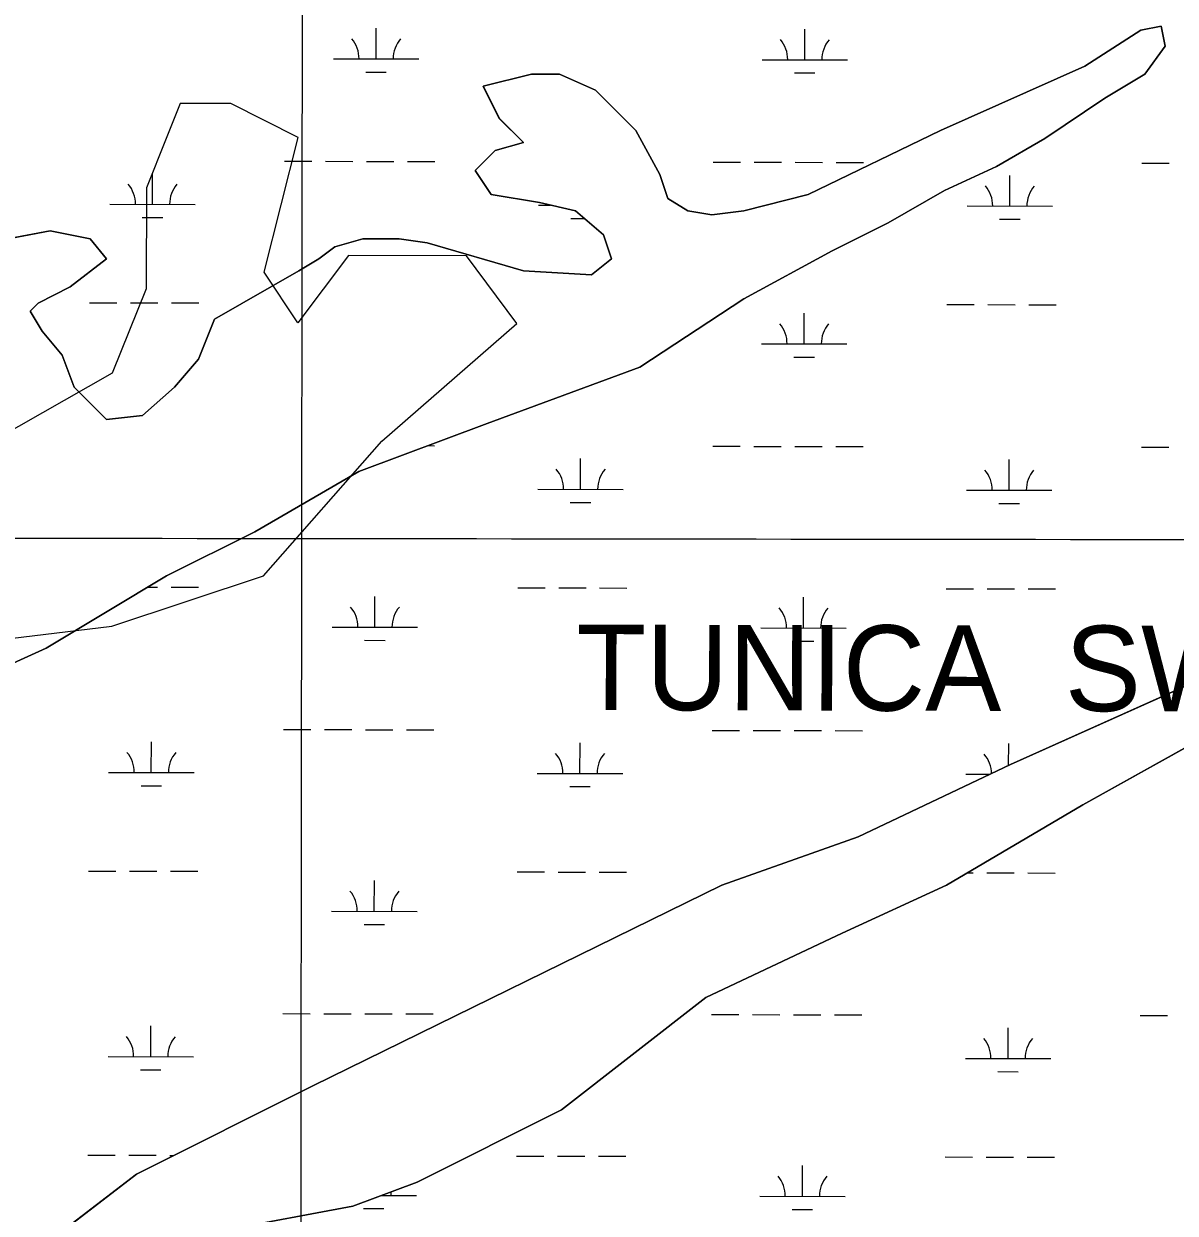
# Model space of a CAD drawing. Extents: x 3219052 to 3256913, y 800770 to 826146.
# Drawn here: x 3238621 to 3239969, y 817496 to 818889 of the extents above; entities that cross this region are included whole.
import ezdxf

# ---------------------------------------------------------------- set-up
doc = ezdxf.new("R2010")
doc.units = 0
for name, color, linetype in [('V-GRID-MAJR', 7, 'Continuous'), ('V-RIVR-IDEN', 7, 'Continuous'), ('V-SITE-VEGE', 7, 'Continuous'), ('V-TOPO-SHOR', 7, 'Continuous'), ('V-WETL-SWMP', 7, 'Continuous')]:
    doc.layers.add(name, color=color, linetype=linetype)

msp = doc.modelspace()

# ---------------------------------------------------------------- linework, layer by layer
at = {"layer": 'V-GRID-MAJR'}
for points in [[(3238932.375, 806165.204), (3238939.4250000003, 812223.951), (3238946.4790000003, 818286.164), (3238953.5330000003, 824348.415), (3238953.537, 824351.841)], [(3223238.921, 818307.868), (3228474.772, 818299.872), (3233710.625, 818292.637), (3238946.4790000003, 818286.164), (3244182.3340000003, 818280.452), (3249418.1890000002, 818275.502), (3254654.045, 818271.314), (3254654.046, 818271.314)]]:
    msp.add_spline(points, degree=3, dxfattribs=at)
at = {"layer": 'V-SITE-VEGE'}
for points in [[(3238595.468, 818134.171), (3238647.119, 818157.6680000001), (3238787.984, 818242.258), (3238891.285, 818293.954), (3239013.369, 818364.448), (3239163.626, 818420.8420000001), (3239342.056, 818486.638), (3239464.14, 818566.528), (3239567.441, 818622.922), (3239633.178, 818655.819), (3239698.914, 818693.414), (3239759.957, 818721.613), (3239816.304, 818754.508), (3239886.736, 818801.506), (3239933.691, 818829.702), (3239957.169, 818862.599), (3239952.473, 818886.096), (3239928.997, 818881.398), (3239863.258, 818839.101), (3239694.22, 818763.906), (3239539.267, 818688.716), (3239464.14, 818669.917), (3239426.575, 818665.2170000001), (3239398.401, 818669.917), (3239374.9250000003, 818684.0160000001), (3239365.5330000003, 818712.213), (3239337.36, 818763.906), (3239290.406, 818810.904), (3239248.145, 818829.702), (3239215.2770000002, 818829.702), (3239158.93, 818815.604), (3239177.713, 818778.007), (3239205.887, 818749.81), (3239173.017, 818740.412), (3239149.538, 818716.9130000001), (3239168.321, 818688.716), (3239224.667, 818679.318), (3239266.928, 818669.917), (3239299.796, 818641.721), (3239309.186, 818613.522), (3239285.71, 818594.725), (3239205.887, 818599.4230000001)], [(3239205.887, 818599.4230000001), (3239093.194, 818632.3200000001), (3239060.325, 818637.02), (3239018.0670000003, 818637.02), (3238985.197, 818627.622), (3238966.414, 818613.522), (3238942.936, 818599.4230000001), (3238844.329, 818543.029), (3238825.549, 818496.034), (3238797.374, 818463.139), (3238759.81, 818430.24), (3238717.552, 818425.542), (3238679.987, 818463.139), (3238665.901, 818500.734), (3238642.423, 818528.931), (3238628.3370000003, 818552.43), (3238637.7290000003, 818561.828), (3238675.291, 818580.627), (3238717.552, 818613.522), (3238698.769, 818637.02), (3238651.815, 818646.421), (3238576.686, 818632.3200000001)], [(3238856.0700000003, 817476.234), (3239006.326, 817504.431), (3239081.455, 817532.628), (3239250.492, 817617.221), (3239419.532, 817748.809), (3239579.18, 817823.9990000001), (3239701.2630000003, 817880.395), (3239860.911, 817974.386), (3240029.951, 818068.377), (3240189.595, 818115.372), (3240283.508, 818152.9670000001), (3240311.68, 818209.363), (3240283.508, 818237.56), (3240227.161, 818237.56), (3240152.032, 818199.965), (3240048.731, 818143.569), (3239776.392, 818021.381), (3239597.9620000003, 817936.789), (3239438.3140000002, 817880.395), (3238959.3710000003, 817645.4180000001), (3238752.769, 817542.029), (3238630.686, 817448.0380000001)]]:
    msp.add_lwpolyline(points, dxfattribs=at)
at = {"layer": 'V-TOPO-SHOR'}
msp.add_lwpolyline([(3238787.544080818, 818754.2792237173), (3238764.427742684, 818696.8378083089), (3238764.1794916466, 818578.3923657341), (3238724.49080159, 818479.770580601), (3238586.138951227, 818401.096578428), (3238467.610758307, 818361.863015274), (3238309.6421263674, 818342.4531095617), (3238250.378029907, 818322.8363279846), (3238250.295279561, 818283.354513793), (3238230.5129972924, 818263.6549818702), (3238289.611593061, 818204.3081350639), (3238565.9015420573, 818164.2470684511), (3238723.870173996, 818183.6569741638), (3238901.662463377, 818242.5073188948), (3239040.1798144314, 818400.1449494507), (3239198.3966974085, 818538.0002977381), (3239139.3394768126, 818617.0880516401), (3239001.153127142, 818617.3776778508), (3238941.764905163, 818538.5381749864), (3238902.40721649, 818597.8436466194), (3238942.220032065, 818755.6881530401), (3238863.339154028, 818795.3354679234), (3238804.1164327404, 818795.4595934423), (3238787.544080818, 818754.2792237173)], dxfattribs=at)
at = {"layer": 'V-WETL-SWMP'}
for p, q in [((3239033.4245650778, 818847.680680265), (3239033.500015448, 818883.6805689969)), ((3239535.3314621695, 818846.6287283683), (3239535.406912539, 818882.6286171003)), ((3239928.995785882, 818881.3910244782), (3239952.472785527, 818886.0900145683)), ((3239952.472785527, 818886.0900145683), (3239957.1687870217, 818862.5930562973)), ((3239863.257788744, 818839.0951043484), (3239928.995785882, 818881.3910244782)), ((3239957.168787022, 818862.5930562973), (3239933.6907891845, 818829.6961166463)), ((3238983.4246749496, 818847.7854755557), (3239083.4244552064, 818847.5758849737)), ((3239485.3315720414, 818846.7335236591), (3239585.3313522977, 818846.5239330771)), ((3239021.3922504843, 818832.2748788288), (3239045.3921977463, 818832.2245770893)), ((3239158.9297918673, 818815.5971915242), (3239215.2767908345, 818829.6961626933)), ((3239215.2767908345, 818829.6961626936), (3239248.1447907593, 818829.6961605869)), ((3239248.1447907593, 818829.6961605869), (3239290.404791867, 818810.8981915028)), ((3239523.2991475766, 818831.2229269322), (3239547.2990948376, 818831.1726251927)), ((3239694.2197939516, 818763.9022496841), (3239863.257788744, 818839.0951043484)), ((3239933.6907891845, 818829.6961166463), (3239886.7357910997, 818801.4991700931)), ((3239177.7117942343, 818778.0012575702), (3239158.9297918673, 818815.5971915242)), ((3239290.404791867, 818810.8981915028), (3239337.3597947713, 818763.902272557)), ((3239886.7357910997, 818801.4991700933), (3239816.3027942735, 818754.5032586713)), ((3239205.8857959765, 818749.8043062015), (3239177.7117942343, 818778.0012575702)), ((3239337.3597947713, 818763.902272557), (3239365.53279802, 818712.2073632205)), ((3239539.2667991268, 818688.710394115), (3239694.219793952, 818763.9022496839)), ((3239173.0167966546, 818740.4053251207), (3239205.8857959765, 818749.8043062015)), ((3239816.3027942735, 818754.5032586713), (3239759.9567965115, 818721.6073211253)), ((3239149.538798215, 818716.9073686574), (3239173.0167966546, 818740.4053251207)), ((3238926.329149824, 818727.8339863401), (3238958.3290795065, 818727.7669173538)), ((3238974.329044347, 818727.7333828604), (3239006.3289740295, 818727.6663138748)), ((3239022.3289388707, 818727.6327793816), (3239054.328868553, 818727.5657103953)), ((3239070.328833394, 818727.5321759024), (3239102.3287630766, 818727.4651069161)), ((3239168.320799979, 818688.7104178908), (3239149.538798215, 818716.9073686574)), ((3239428.236046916, 818726.7820344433), (3239460.2359765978, 818726.7149654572)), ((3239476.235941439, 818726.6814309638), (3239508.2358711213, 818726.614361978)), ((3239524.2358359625, 818726.5808274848), (3239556.235765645, 818726.5137584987)), ((3239572.235730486, 818726.4802240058), (3239604.235660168, 818726.4131550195)), ((3239759.9567965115, 818721.6073211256), (3239698.914798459, 818693.4093754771)), ((3239930.142944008, 818725.7300825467), (3239962.1428736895, 818725.6630135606)), ((3238771.631142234, 818677.4161534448), (3238771.7065926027, 818713.4160421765)), ((3239365.53279802, 818712.2073632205), (3239374.923799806, 818684.0104130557)), ((3239775.444936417, 818675.3122496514), (3239775.5203867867, 818711.3121383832)), ((3239224.667800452, 818679.3114310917), (3239168.320799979, 818688.7104178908)), ((3239464.138800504, 818669.9124325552), (3239539.2667991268, 818688.710394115)), ((3239698.914798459, 818693.4093754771), (3239633.1778010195, 818655.8134469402)), ((3238721.6312521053, 818677.5209487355), (3238821.6310323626, 818677.3113581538)), ((3239223.538149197, 818676.4689968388), (3239237.5800591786, 818676.4395662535)), ((3239266.9268009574, 818669.9124451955), (3239224.667800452, 818679.3114310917)), ((3239374.923799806, 818684.0104130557), (3239398.4018006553, 818669.9124367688)), ((3239725.4450462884, 818675.4170449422), (3239825.4448265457, 818675.2074543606)), ((3238759.5988276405, 818662.0103520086), (3238783.598774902, 818661.9600502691)), ((3239261.5057247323, 818660.9584001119), (3239277.4029409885, 818660.9250809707)), ((3239299.795802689, 818641.7144935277), (3239266.9268009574, 818669.9124451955)), ((3239398.4018006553, 818669.9124367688), (3239426.574800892, 818665.2124433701)), ((3239426.574800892, 818665.2124433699), (3239464.138800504, 818669.9124325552)), ((3239763.412621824, 818659.9064482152), (3239787.412569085, 818659.8561464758)), ((3238576.685804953, 818632.3155566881), (3238651.813803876, 818646.4145266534)), ((3238651.813803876, 818646.4145266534), (3238698.769804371, 818637.015540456)), ((3239633.1778010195, 818655.8134469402), (3239567.4408032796, 818622.9165099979)), ((3238698.769804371, 818637.015540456), (3238717.551805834, 818613.517581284)), ((3238985.1958043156, 818627.61653891), (3239018.0648036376, 818637.0155199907)), ((3239018.0648036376, 818637.0155199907), (3239060.3248035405, 818637.0155172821)), ((3239060.3248035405, 818637.0155172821), (3239093.192803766, 818632.3155235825)), ((3239093.192803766, 818632.3155235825), (3239205.8858056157, 818599.4185752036)), ((3239309.186804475, 818613.5175433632), (3239299.795802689, 818641.7144935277)), ((3238966.413805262, 818613.5175653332), (3238985.1958043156, 818627.61653891)), ((3239567.4408032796, 818622.9165099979), (3239464.138807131, 818566.5226174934)), ((3238717.551805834, 818613.517581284), (3238675.2918080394, 818580.620642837)), ((3238942.9368062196, 818599.4185920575), (3238966.4138052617, 818613.5175653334)), ((3239285.708805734, 818594.7195784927), (3239309.186804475, 818613.5175433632)), ((3238844.3308100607, 818543.0246992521), (3238942.9368062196, 818599.4185920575)), ((3239205.8858056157, 818599.4185752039), (3239285.708805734, 818594.7195784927)), ((3238675.2918080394, 818580.620642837), (3238637.7278093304, 818561.8226788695)), ((3239464.138807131, 818566.5226174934), (3239342.0558125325, 818486.6297682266)), ((3238637.7278093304, 818561.8226788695), (3238628.3368099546, 818552.4236962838)), ((3238628.3368099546, 818552.4236962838), (3238642.422811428, 818528.925737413)), ((3238697.981376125, 818562.1383664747), (3238729.9813058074, 818562.0712974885)), ((3238745.981270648, 818562.0377629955), (3238777.9812003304, 818561.9706940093)), ((3238793.9811651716, 818561.9371595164), (3238825.9810948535, 818561.8700905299)), ((3239534.6342274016, 818513.9547565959), (3239534.7096777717, 818549.9546453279)), ((3239701.795170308, 818560.0344626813), (3239733.795099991, 818559.9673936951)), ((3239749.7950648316, 818559.9338592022), (3239781.7949945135, 818559.866790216)), ((3239797.794959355, 818559.833255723), (3239829.794889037, 818559.7661867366)), ((3238825.5488131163, 818496.0297845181), (3238844.3308100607, 818543.0246992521)), ((3238642.422811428, 818528.925737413), (3238665.9008131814, 818500.7287863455)), ((3239484.634337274, 818514.0595518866), (3239584.63411753, 818513.8499613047)), ((3238665.9008131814, 818500.7287863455), (3238679.9868155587, 818463.1328526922)), ((3238797.3748152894, 818463.1328451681), (3238825.5488131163, 818496.0297845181)), ((3239522.6019128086, 818498.5489551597), (3239546.60186007, 818498.4986534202)), ((3239342.0558125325, 818486.6297682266), (3239163.625817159, 818420.83689735)), ((3238679.9868155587, 818463.1328526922), (3238717.551817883, 818425.5359175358)), ((3238759.810817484, 818430.2359064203), (3238797.3748152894, 818463.1328451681)), ((3238717.551817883, 818425.5359175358), (3238759.810817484, 818430.2359064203)), ((3239163.625817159, 818420.8368973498), (3239013.368821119, 818364.4420078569)), ((3239094.271304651, 818394.8065615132), (3239101.631528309, 818394.7911351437)), ((3239427.5388121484, 818394.1080626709), (3239459.5387418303, 818394.0409936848)), ((3239475.5387066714, 818394.0074591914), (3239507.5386363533, 818393.9403902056)), ((3239523.5386011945, 818393.9068557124), (3239555.5385308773, 818393.8397867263)), ((3239571.538495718, 818393.8062522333), (3239603.5384254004, 818393.7391832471)), ((3239929.44570924, 818393.0561107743), (3239961.4456389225, 818392.9890417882)), ((3239272.840804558, 818343.6902297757), (3239272.9162549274, 818379.6901185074)), ((3239774.7477016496, 818342.638277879), (3239774.8231520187, 818378.6381666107)), ((3239013.368821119, 818364.4420078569), (3238891.2858259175, 818293.9491417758)), ((3239222.8409144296, 818343.7950250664), (3239322.840694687, 818343.5854344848)), ((3239724.747811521, 818342.7430731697), (3239824.747591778, 818342.533482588)), ((3239260.8084899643, 818328.2844283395), (3239284.8084372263, 818328.2341266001)), ((3239762.7153870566, 818327.2324764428), (3239786.7153343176, 818327.1821747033)), ((3238891.2858259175, 818293.9491417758), (3238787.9838294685, 818242.2542408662)), ((3238787.9838294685, 818242.2542408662), (3238647.1188352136, 818157.6634012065)), ((3238766.4441398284, 818229.319441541), (3238777.283965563, 818229.2967222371)), ((3238793.2839304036, 818229.2631877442), (3238825.2838600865, 818229.1961187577)), ((3239199.1910384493, 818228.4124428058), (3239231.190968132, 818228.3453738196)), ((3239247.190932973, 818228.3118393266), (3239279.1908626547, 818228.2447703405)), ((3239295.1908274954, 818228.2112358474), (3239327.1907571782, 818228.1441668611)), ((3239032.030095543, 818182.3327367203), (3239032.1055459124, 818218.3326254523)), ((3239533.936992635, 818181.2807848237), (3239534.0124430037, 818217.2806735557)), ((3239701.097935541, 818227.3604909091), (3239733.0978652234, 818227.293421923)), ((3239749.0978300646, 818227.25988743), (3239781.0977597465, 818227.1928184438)), ((3239797.0977245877, 818227.1592839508), (3239829.0976542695, 818227.0922149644)), ((3238982.0302054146, 818182.4375320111), (3239082.029985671, 818182.2279414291)), ((3239483.9371025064, 818181.3855801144), (3239583.936882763, 818181.1759895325)), ((3239019.99778095, 818166.9269352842), (3239043.997728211, 818166.8766335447)), ((3239521.904678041, 818165.8749833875), (3239545.904625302, 818165.824681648)), ((3238647.1188352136, 818157.6634012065), (3238595.467836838, 818134.165446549)), ((3239776.3918413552, 818021.3765726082), (3240048.731832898, 818143.5643365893)), ((3238924.934680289, 818062.4860427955), (3238956.934609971, 818062.4189738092)), ((3238972.934574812, 818062.3854393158), (3239004.9345044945, 818062.3183703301)), ((3239020.9344693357, 818062.2848358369), (3239052.934399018, 818062.2177668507)), ((3239068.9343638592, 818062.1842323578), (3239100.934293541, 818062.1171633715)), ((3239426.841577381, 818061.4340908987), (3239458.841507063, 818061.3670219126)), ((3239474.841471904, 818061.3334874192), (3239506.8414015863, 818061.2664184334)), ((3239522.8413664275, 818061.2328839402), (3239554.8412961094, 818061.1658149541)), ((3239570.8412609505, 818061.1322804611), (3239602.841190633, 818061.0652114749)), ((3240029.949837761, 818068.3724722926), (3239860.9108441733, 817974.381651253)), ((3238770.2366726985, 818012.0682099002), (3238770.312123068, 818048.0680986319)), ((3239272.1435697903, 818011.0162580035), (3239272.21902016, 818047.0161467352)), ((3239774.072080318, 818020.276797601), (3239774.1259172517, 818045.9641948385)), ((3239597.961847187, 817936.784735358), (3239776.3918413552, 818021.3765726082)), ((3238720.23678257, 818012.1730051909), (3238820.236562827, 818011.9634146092)), ((3239222.1436796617, 818011.1210532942), (3239322.143459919, 818010.9114627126)), ((3239724.050576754, 818010.0691013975), (3239752.415535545, 818010.0096509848)), ((3238758.204358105, 817996.662408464), (3238782.2043053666, 817996.6121067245)), ((3239260.1112551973, 817995.6104565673), (3239284.1112024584, 817995.5601548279)), ((3239860.9108441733, 817974.381651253), (3239701.262850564, 817880.3908296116)), ((3239438.313851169, 817880.3908464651), (3239597.961847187, 817936.784735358)), ((3238696.58690659, 817896.7904229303), (3238728.5868362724, 817896.7233539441)), ((3238744.586801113, 817896.6898194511), (3238776.5867307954, 817896.622750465)), ((3238792.5866956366, 817896.589215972), (3238824.5866253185, 817896.5221469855)), ((3239198.493803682, 817895.7384710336), (3239230.493733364, 817895.6714020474)), ((3239246.493698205, 817895.6378675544), (3239278.493627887, 817895.5707985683)), ((3239294.493592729, 817895.5372640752), (3239326.4935224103, 817895.4701950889)), ((3239725.455580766, 817894.6340063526), (3239732.400630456, 817894.6194501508)), ((3239748.400595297, 817894.5859156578), (3239780.4005249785, 817894.5188466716)), ((3239796.40048982, 817894.4853121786), (3239828.4004195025, 817894.4182431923)), ((3238959.370867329, 817645.414297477), (3239438.313851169, 817880.3908464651)), ((3239031.3328607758, 817849.6587649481), (3239031.408311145, 817885.6586536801)), ((3239701.262850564, 817880.3908296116), (3239579.17985446, 817823.9959383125)), ((3238981.332970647, 817849.7635602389), (3239081.3327509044, 817849.5539696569)), ((3239019.300546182, 817834.252963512), (3239043.3004934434, 817834.2026617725)), ((3239579.17985446, 817823.9959383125), (3239419.531859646, 817748.8040830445)), ((3239419.531859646, 817748.8040830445), (3239250.492868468, 817617.2173292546)), ((3238924.2374455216, 817729.8120710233), (3238956.237375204, 817729.745002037)), ((3238972.237340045, 817729.7114675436), (3239004.237269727, 817729.644398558)), ((3239020.237234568, 817729.6108640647), (3239052.2371642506, 817729.5437950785)), ((3239068.2371290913, 817729.5102605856), (3239100.237058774, 817729.4431915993)), ((3239426.1443426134, 817728.7601191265), (3239458.1442722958, 817728.6930501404)), ((3239474.1442371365, 817728.659515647), (3239506.144166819, 817728.5924466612)), ((3239522.1441316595, 817728.558912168), (3239554.1440613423, 817728.4918431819)), ((3239570.144026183, 817728.458308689), (3239602.1439558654, 817728.3912397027)), ((3239928.051239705, 817727.7081672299), (3239960.0511693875, 817727.6410982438)), ((3238769.539437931, 817679.394238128), (3238769.6148883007, 817715.3941268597)), ((3239773.353232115, 817677.2903343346), (3239773.4286824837, 817713.2902230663)), ((3238719.539547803, 817679.4990334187), (3238819.53932806, 817679.289442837)), ((3239723.3533419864, 817677.3951296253), (3239823.3531222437, 817677.1855390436)), ((3238757.5071233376, 817663.9884366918), (3238781.5070705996, 817663.9381349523)), ((3239761.3209175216, 817661.8845328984), (3239785.3208647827, 817661.834231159)), ((3238752.767874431, 817542.0244956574), (3238959.370867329, 817645.414297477)), ((3239250.4928684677, 817617.2173292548), (3239081.454874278, 817532.6254914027)), ((3238695.8896718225, 817564.1164511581), (3238727.889601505, 817564.049382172)), ((3238743.8895663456, 817564.0158476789), (3238775.889496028, 817563.9487786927)), ((3238791.889460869, 817563.9152441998), (3238796.4926982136, 817563.9055962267)), ((3239197.7965689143, 817563.0644992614), (3239229.7964985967, 817562.9974302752)), ((3239245.796463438, 817562.9638957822), (3239277.7963931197, 817562.8968267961)), ((3239293.796357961, 817562.863292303), (3239325.796287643, 817562.7962233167)), ((3239699.703466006, 817562.0125473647), (3239731.703395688, 817561.9454783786)), ((3239747.703360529, 817561.9119438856), (3239779.703290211, 817561.8448748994)), ((3239795.7032550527, 817561.8113404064), (3239827.7031847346, 817561.7442714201)), ((3239532.5425230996, 817515.9328412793), (3239532.6179734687, 817551.9327300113)), ((3238630.6848807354, 817448.0336716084), (3238752.767874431, 817542.0244956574)), ((3239081.454874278, 817532.6254914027), (3239006.325876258, 817504.4285466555)), ((3239006.325876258, 817504.4285466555), (3238856.0698784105, 817476.2306067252)), ((3239039.730421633, 817516.9657312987), (3239080.6355161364, 817516.8799978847)), ((3239482.542632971, 817516.03763657), (3239582.542413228, 817515.8280459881)), ((3239018.6033114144, 817501.5789917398), (3239042.6032586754, 817501.5286900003)), ((3239520.5102085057, 817500.5270398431), (3239544.5101557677, 817500.4767381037))]:
    msp.add_line(p, q, dxfattribs=at)
for centre, radius, start, end in [((3238978.1827454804, 818848.2712659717), 35.24628790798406, 359.1080939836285, 40.65175231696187), ((3239088.6683749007, 818848.0396979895), 35.246287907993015, 139.10808960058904, 180.65174793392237), ((3239480.0896425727, 818847.219314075), 35.24628790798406, 359.1080939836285, 40.65175231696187), ((3239590.575271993, 818846.9877460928), 35.246287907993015, 139.10808960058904, 180.65174793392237), ((3238716.389322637, 818678.0067391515), 35.24628790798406, 359.1080939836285, 40.65175231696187), ((3238826.874952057, 818677.7751711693), 35.246287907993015, 139.10808960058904, 180.65174793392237), ((3239720.20311682, 818675.9028353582), 35.24628790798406, 359.1080939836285, 40.65175231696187), ((3239830.68874624, 818675.6712673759), 35.246287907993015, 139.10808960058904, 180.65174793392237), ((3239479.3924078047, 818514.5453423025), 35.24628790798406, 359.1080939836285, 40.65175231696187), ((3239589.878037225, 818514.3137743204), 35.246287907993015, 139.10808960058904, 180.65174793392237), ((3239217.5989849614, 818344.2808154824), 35.24628790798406, 359.1080939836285, 40.65175231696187), ((3239328.0846143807, 818344.0492475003), 35.246287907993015, 139.10808960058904, 180.65174793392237), ((3239719.505882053, 818343.2288635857), 35.24628790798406, 359.1080939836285, 40.65175231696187), ((3239829.991511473, 818342.9972956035), 35.246287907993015, 139.10808960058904, 180.65174793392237), ((3238976.788275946, 818182.9233224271), 35.24628790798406, 359.1080939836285, 40.65175231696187), ((3239087.273905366, 818182.6917544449), 35.246287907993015, 139.10808960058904, 180.65174793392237), ((3239478.6951730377, 818181.8713705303), 35.24628790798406, 359.1080939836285, 40.65175231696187), ((3239589.1808024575, 818181.6398025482), 35.246287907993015, 139.10808960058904, 180.65174793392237), ((3238714.9948531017, 818012.6587956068), 35.24628790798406, 359.1080939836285, 40.65175231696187), ((3238825.4804825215, 818012.4272276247), 35.246287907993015, 139.10808960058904, 180.65174793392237), ((3239216.9017501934, 818011.6068437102), 35.24628790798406, 359.1080939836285, 40.65175231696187), ((3239327.3873796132, 818011.3752757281), 35.246287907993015, 139.10808960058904, 180.65174793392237), ((3239718.8086472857, 818010.5548918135), 35.24628790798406, 0.3765230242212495, 40.651752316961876), ((3239829.294276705, 818010.3233238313), 35.246287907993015, 139.10808960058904, 139.9364566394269), ((3238976.0910411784, 817850.2493506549), 35.24628790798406, 359.1080939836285, 40.65175231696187), ((3239086.5766705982, 817850.0177826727), 35.246287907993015, 139.10808960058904, 180.65174793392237), ((3238714.2976183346, 817679.9848238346), 35.24628790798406, 359.1080939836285, 40.65175231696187), ((3238824.783247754, 817679.7532558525), 35.246287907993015, 139.10808960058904, 180.65174793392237), ((3239718.111412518, 817677.8809200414), 35.24628790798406, 359.1080939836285, 40.65175231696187), ((3239828.597041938, 817677.6493520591), 35.246287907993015, 139.10808960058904, 180.65174793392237), ((3239477.3007035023, 817516.523426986), 35.24628790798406, 359.1080939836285, 40.65175231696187), ((3239587.786332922, 817516.2918590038), 35.246287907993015, 139.10808960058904, 180.65174793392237), ((3239085.8794358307, 817517.3438109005), 35.246287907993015, 173.82613939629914, 180.65174793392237)]:
    msp.add_arc(centre, radius, start, end, dxfattribs=at)

# ---------------------------------------------------------------- texts
at = {"layer": 'V-RIVR-IDEN'}
msp.add_text('TUNICA  SWAMP', height=99.99980199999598, rotation=359.8799133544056, dxfattribs=at).set_placement((3239267.7294274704, 818085.2948020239))

doc.saveas('drawing.dxf')
